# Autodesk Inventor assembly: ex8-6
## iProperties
Author: J. DESIGNER
Created: 2001-10
Part Number: ex8-6
Document SubType Name: Assembly
Designer: J. DESIGNER
Control State: 0
Master: False
Checked Out: False
PropertySet Name: Design Tracking Control
Shininess: 64.0
Angle Display Precision: 2
Document Length Units: 11272
Document Angle Units: 11286
Document Time Units: 11279
Document Mass Units: 11290
Document Length Units Precision: 3
Document Angle Units Precision: 2
Compacted: True
PropertySet Name: _Private Model Information
Density: 0.0
Volumn: 0.0
Area: 0.0
PropertySet Name: Model Information
